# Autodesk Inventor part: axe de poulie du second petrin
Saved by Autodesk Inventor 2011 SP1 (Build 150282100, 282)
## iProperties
Created: 2010-12
Part Number: axe de poulie du second petrin
Document SubType Name: Modeling
Designer: eric
Density: 1 g/cm^3
Mass: 3.03947 g
Surface Area: 15.398 cm^2
Volume: 3.03947 cm^3
Author: eric
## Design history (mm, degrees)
feature "Base1"
node "Solide1"
node "Corps solides"
node "Corps surfaciques"
